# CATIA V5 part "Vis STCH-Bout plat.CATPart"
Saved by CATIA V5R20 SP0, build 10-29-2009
Part number: Vis STHC M 2x2,5
Material "Acier": density 7860 kg/m3, Young's modulus 2e+11 Pa, Poisson ratio 0.266, thermal expansion 1.17e-05 1/K
Bounding box of the stored display mesh (mm): x -0.96 to 0.96, y -0.96 to 0.96, z 0 to 2.5
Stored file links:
  C:\travail\CAO\bib catia\vis\Vis STCH-Bout plat.CATPart
  C:\Program Files\Dassault Systemes\B20\win_b64\startup\materials\French\Catalog.CATMaterial
  C:\Program Files\Dassault Systemes\B20\win_b64\reffiles\standard\MetricThickPitch.txt
  C:\travail\CAO\bib catia\vis\vis-HTSC_BP.xls
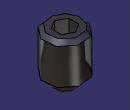
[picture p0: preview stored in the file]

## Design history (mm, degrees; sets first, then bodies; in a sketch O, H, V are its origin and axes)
Parameters
  d = 2 mm {design table}
  dp = 1 mm {design table}
  t = 1.7 mm {design table}
  s = 0.9 mm {design table}
  p = 0.4 mm {design table}
  l = 2.5 mm {design table}
  Designation = "Vis STHC M 2x2,5" {design table}
  dn = "M2" {design table}
Body1 (main body)
  Sketch1 on yz-plane, origin (0, 0, 0), H (0, 1, 0), V (0, 0, 1)
    axis line L1 (0, 0) -> (0, 10.0456)
    line L2 (0, 0) -> (-0.5, 0)
    point P2 (-0.5, 0)
    line L3 (-0.5, 0) -> (-1, 0.5)
    line L4 (-1, 0.5) -> (-1, 2.5)
    line L5 (-1, 2.5) -> (0, 2.5)
    point P5 (0, 2.5)
    line L6 (0, 2.5) -> (0, 0)
    "Radius" L4 L1 = 1 {= d /2}
    distance L2 L5 = 2.5 {= l}
    "Radius" P2 L1 = 0.5 {= dp /2}
    angle L2 L3 = 45
    vertical: L1 V, L4 V, L6 V
    horizontal: L2 H, L5 H
    coincidence: P5 L1
  Shaft1: profile Sketch1, axis Sketch1.L1, angle 360
  Thread1: "M2", diameter 2, depth 2, pitch 0.4, on face of Shaft1 from Sketch1.L4, from face of Shaft1 from Sketch1.L5
  Chamfer1: length 0.2 {= p /2}, angle 45, on edge [face of Shaft1 from Sketch1.L4 | face of Shaft1 from Sketch1.L5]
  Sketch2 on face of Shaft1 from Sketch1.L5, origin (0, 0, 2.5), H (1, 0, 0), V (0, 1, 0)
    point P1 (0, 0)
    point P2 (0.45, -0.2598)
    point P3 (0.45, 0.2598)
    point P4 (0, 0.5196)
    point P5 (-0.45, 0.2598)
    point P6 (-0.45, -0.2598)
    point P7 (0, -0.5196)
    point P8 (0.45, 0)
    line L1 (0.45, -0.2598) -> (0.45, 0.2598)
    line L2 (0.45, 0.2598) -> (0, 0.5196)
    line L3 (0, 0.5196) -> (-0.45, 0.2598)
    line L4 (-0.45, 0.2598) -> (-0.45, -0.2598)
    line L5 (-0.45, -0.2598) -> (0, -0.5196)
    line L6 (0, -0.5196) -> (0.45, -0.2598)
    construction line L7 (0, 0) -> (0.45, 0)
    construction circle A1 centre (0, 0) radius 0.5196
    construction arc A2 centre (-0.45, -0.2598) radius 0.5196 from (-0.45, 0.2598) to (0, -0.5196) cw
    construction arc A3 centre (0.45, 0.2598) radius 0.5196 from (0, 0.5196) to (0.45, -0.2598) ccw
    distance L4 L1 = 0.9 {= s}
    coincidence: P1 H, A1 P2, A1 P3, A1 P4, A1 P5, A1 P6, A1 P7, A2 P1, A3 P1, P1 O
    horizontal: L7 H
    midpoint: P8 L1
  Pocket1: profile Sketch2, direction (0, 0, -1), length 1.7 {= t}
Relations
  Thread1.ThreadDescription = dn
  design table, configuration 1, drives dn, d, p, dp, s, t, l, Designation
